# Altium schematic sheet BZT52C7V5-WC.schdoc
size 127 x 101 mm
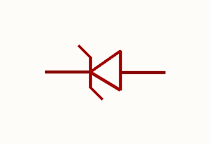
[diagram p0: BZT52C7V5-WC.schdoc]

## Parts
D?  bzt52c7v5_c364302  [SOD-123_L2.7-W1.6-LS3.7-RD-1]  (value not drawn)

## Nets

Not connected (* = marked no-connect by the designer): D? 1 2

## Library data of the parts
D? = bzt52c7v5_c364302: 二极管配置:1个独立式;稳压值(标称值):7.5V;稳压值(范围值):7.13V~7.88V;耗散功率(Pd):500mW;; Manufacturer: MDD(辰达半导体); Symbol: BZT52C7V5-WC; AddInBom: yes; ModelId: 528459655f7d4601a76356f3191c812b; ModelTransform: 151.575,66.929,0,0,0,0,0,0,0; Diode Configuration: 1个独立式; Zener Voltage(Nom): 7.5V; Reverse Leakage Current (Ir): 500nA@4V; Pd - Power Dissipation: 500mW; Impedance(Zzt): 30Ω; Tolerance: ±5%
